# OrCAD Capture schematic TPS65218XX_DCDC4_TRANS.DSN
size E; title: TPS65218D0 Power Management for ARM® Cortex™-A8/A9; rev: 1.0; note: Datasheet:SLDS234B     EVM:NA; note: Synchronous Step Down Converter
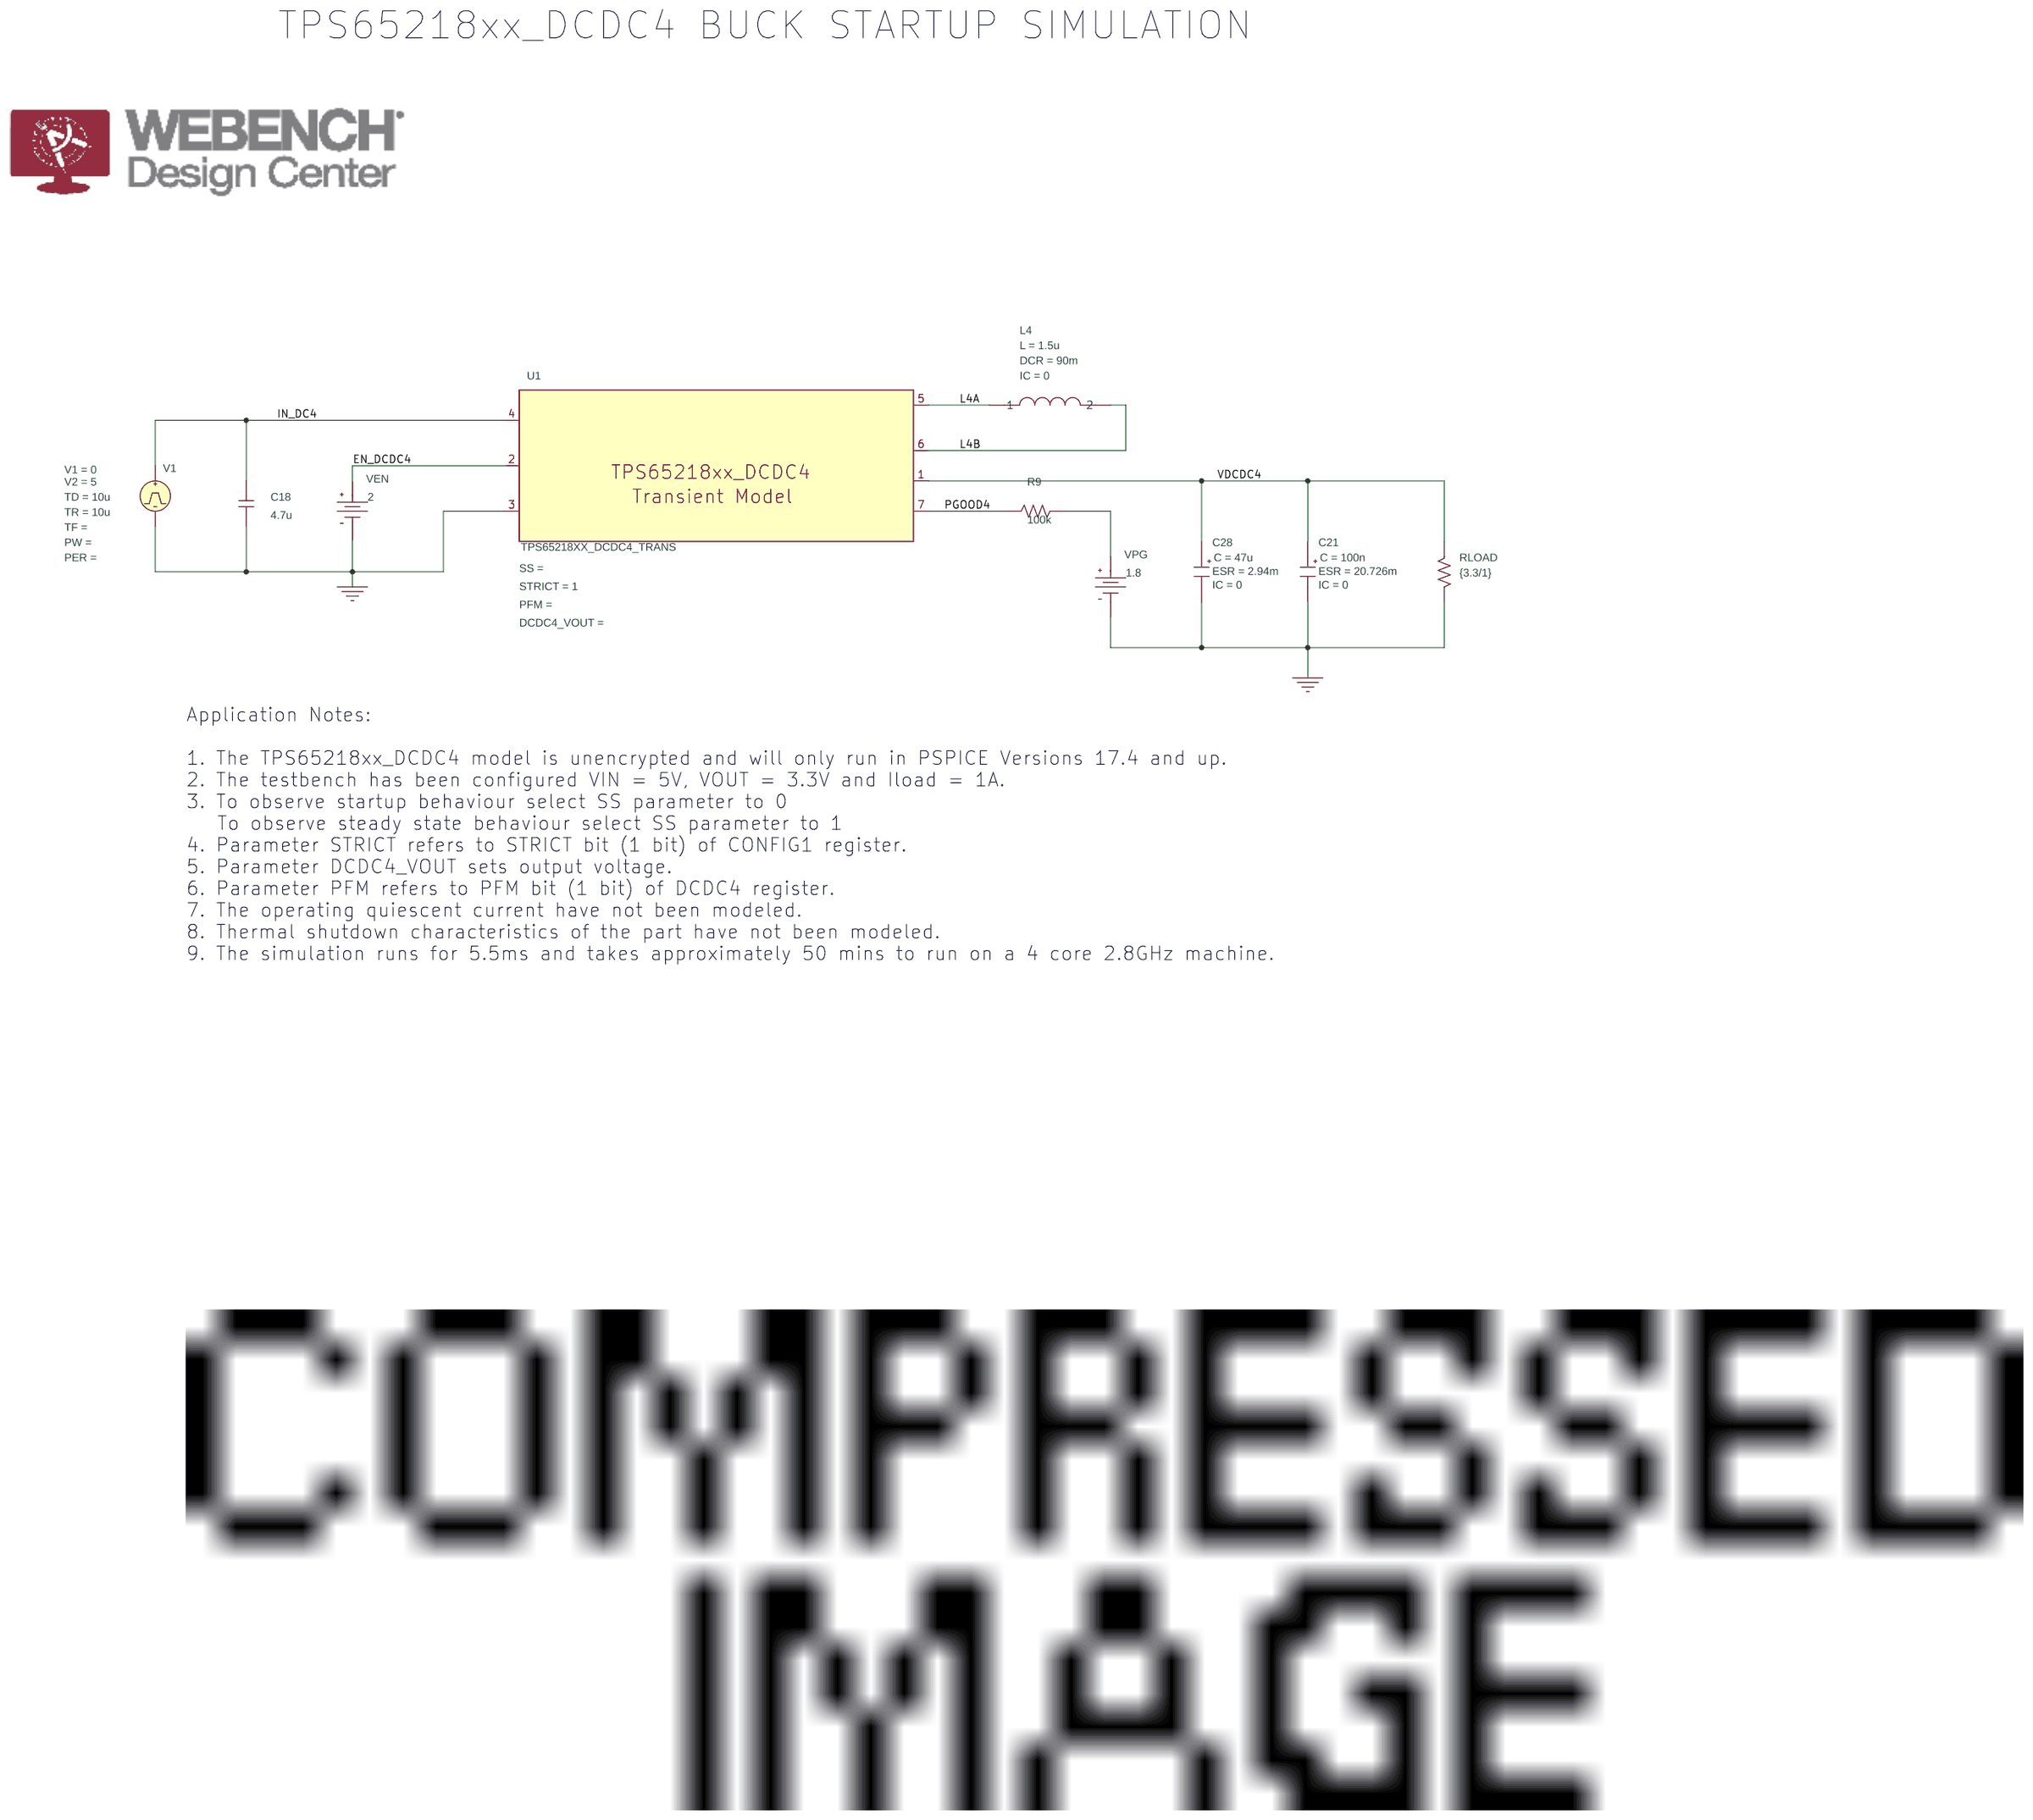
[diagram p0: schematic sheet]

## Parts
C18  4.7u  [RAD/CK05]
C21  CESR
C28  CESR
L4  LDCR
R9  100k  [AX/RC05]
RLOAD  {3.3/1}  [AX/RC05]
U1  TPS65218XX_DCDC4_TRANS
V1  VPULSE
VEN  VDC
VPG  VDC

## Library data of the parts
C18 = C
C21 = CESR_0: C: 100n; ESR: 20.726m; IC: 0; PSpiceTemplate: X^@REFDES %IN %OUT @MODEL PARAMS:  ?C|C=@C||C=100u|  ?ESR|ESR=@ESR||ESR=0.01| ?X|X=@X||X=2|  ?IC|IC=@IC||IC=2|; X: 1
C28 = CESR_0: C: 47u; ESR: 2.94m; IC: 0; PSpiceTemplate: X^@REFDES %IN %OUT @MODEL PARAMS:  ?C|C=@C||C=100u|  ?ESR|ESR=@ESR||ESR=0.01| ?X|X=@X||X=2|  ?IC|IC=@IC||IC=2|; X: 1
L4 = LDCR: DCR: 90m; IC: 0; L: 1.5u
R9 RLOAD = R
U1 = TPS65218XX_DCDC4_TRANS: STRICT: 1
V1 = VPULSE: TD: 10u; TR: 10u; V1: 0; V2: 5
VEN = VDC: DC: 2
VPG = VDC: DC: 1.8

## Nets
0: C18.1 C21.2(OUT) C28.2(OUT) RLOAD.2 U1.3(POWER_PAD) V1.2(-) VEN.1(-) VPG.1(-)
EN_DCDC4: U1.2(EN_DCDC4) VEN.0(+)
IN_DC4: C18.2 U1.4(IN_DCDC4) V1.1(+)
L4A: L4.1 U1.5(L4A)
L4B: L4.2 U1.6(L4B)
PGOOD4: R9.1 U1.7(PGOOD4)
VDCDC4: C21.1(IN) C28.1(IN) RLOAD.1 U1.1(DCDC4)
N16775055: R9.2 VPG.0(+)

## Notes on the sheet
- TPS65218xx_DCDC4 BUCK STARTUP SIMULATION
- Application Notes:
  1. The TPS65218xx_DCDC4 model is unencrypted and will only run in PSPICE Versions 17.4 and up.
  2. The testbench has been configured VIN = 5V, VOUT = 3.3V and Iload = 1A.
  3. To observe startup behaviour select SS parameter to 0
     To observe steady state behaviour select SS parameter to 1
  4. Parameter STRICT refers to STRICT bit (1 bit) of CONFIG1 register.
  5. Parameter DCDC4_VOUT sets output voltage.
  6. Parameter PFM refers to PFM bit (1 bit) of DCDC4 register.
  7. The operating quiescent current have not been modeled.
  8. Thermal shutdown characteristics of the part have not been modeled.
  9. The simulation runs for 5.5ms and takes approximately 50 mins to run on a 4 core 2.8GHz machine.
